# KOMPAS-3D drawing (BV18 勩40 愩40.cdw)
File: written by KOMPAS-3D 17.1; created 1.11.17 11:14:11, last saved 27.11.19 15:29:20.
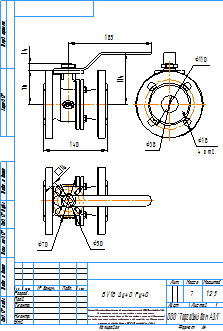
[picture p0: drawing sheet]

Sheet 1: A4, portrait

Title block, sheet 1: name: BV18 Ду40 Ру40; mass: 7; sheets: 1; sheet format: A4; stored path: C:\Users\kka\KOMPAS_Work\!Trash\BV18\KOMPAS 2D\BV18 Ду50 Ру40.cdw

Views: Проекционный вид 4, Проекционный вид 6
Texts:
  kka
  adl
  Рама для чертежей
  Лит-Масса-Масштаб
  Материал-Предприятие
  Масштаб
  Изм.
  Лист
  № докум.
  Подп.
  Дата
  Лит.
  Разраб.
  Пров.
  Т.контр.
  Листов
  Внимание! Данный продукт является объектом авторского права ООО «Торговый Дом АДЛ».
  Запрещается изменение, копирование, распространение
  (в том числе путем копирования на другие сайты и ресурсы в Интернете)
  или любое иное использование информации и объектов без предварительного
  согласия правообладателя (ООО «Торговый Дом АДЛ»).
  Н.контр.
  Утв.
  ООО "Торговый дом АДЛ"
  Изменение
  Номер документа
  Подпись
  Обозначение документа
  Наименование изделия
  Масса изделия по ГОСТ 2.109-73
  Порядковый номер листа
  Общее количество листов в документе
  Характер работы, выполненной лицом, подписавшим документ
  Наименование или индекс предприятия, выпускающего документ
  Инв. № подл.
  Подп. и дата
  Взам. инв. №
  Инв. № дубл.
  Инвентарный номер подлинника по ГОСТ 2.501-68
  Подпись принявшего подлинник в отдел технической документации
  Инвентарный номер подлинника, взамен которого выпущен данный подлинник
  Инвентарный номер дубликата по ГОСТ 2.502-68
  Подпись принявшего дубликат в отдел технической документации
  Справ. №
  Перв. примен.
  Обозначение документа, взамен или на основании которого выпущен данный документ
  Обозначение документа, в котором впервые записан данный документ
  Подпись лица, копировавшего чертеж
  Обозначение формата листа
  !Рама для чертежа
Dimensions and other numbers on the sheet: 140; 76; 14; 185; 114; 70; 50; 1:2,5; 1; 7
